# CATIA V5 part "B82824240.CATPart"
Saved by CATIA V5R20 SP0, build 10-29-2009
Part number: B82824240
Revision: 5
Definition: design
Nomenclature: B82824240
Source: made
Description: NOT SPECIFIED
Bounding box of the stored display mesh (mm): x -14 to 14, y -14 to 14, z 0 to 240
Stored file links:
  C:\Users\Raffaele\Desktop\3D X SITO CF\BOLEX\7-PILLAR REF 828\B82824240.CATPart
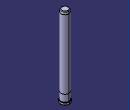
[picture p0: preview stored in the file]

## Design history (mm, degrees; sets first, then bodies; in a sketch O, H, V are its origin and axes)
Body1 "MANIFOLD_SOLID_BREP #450" (main body)
  Solid1: solid without history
